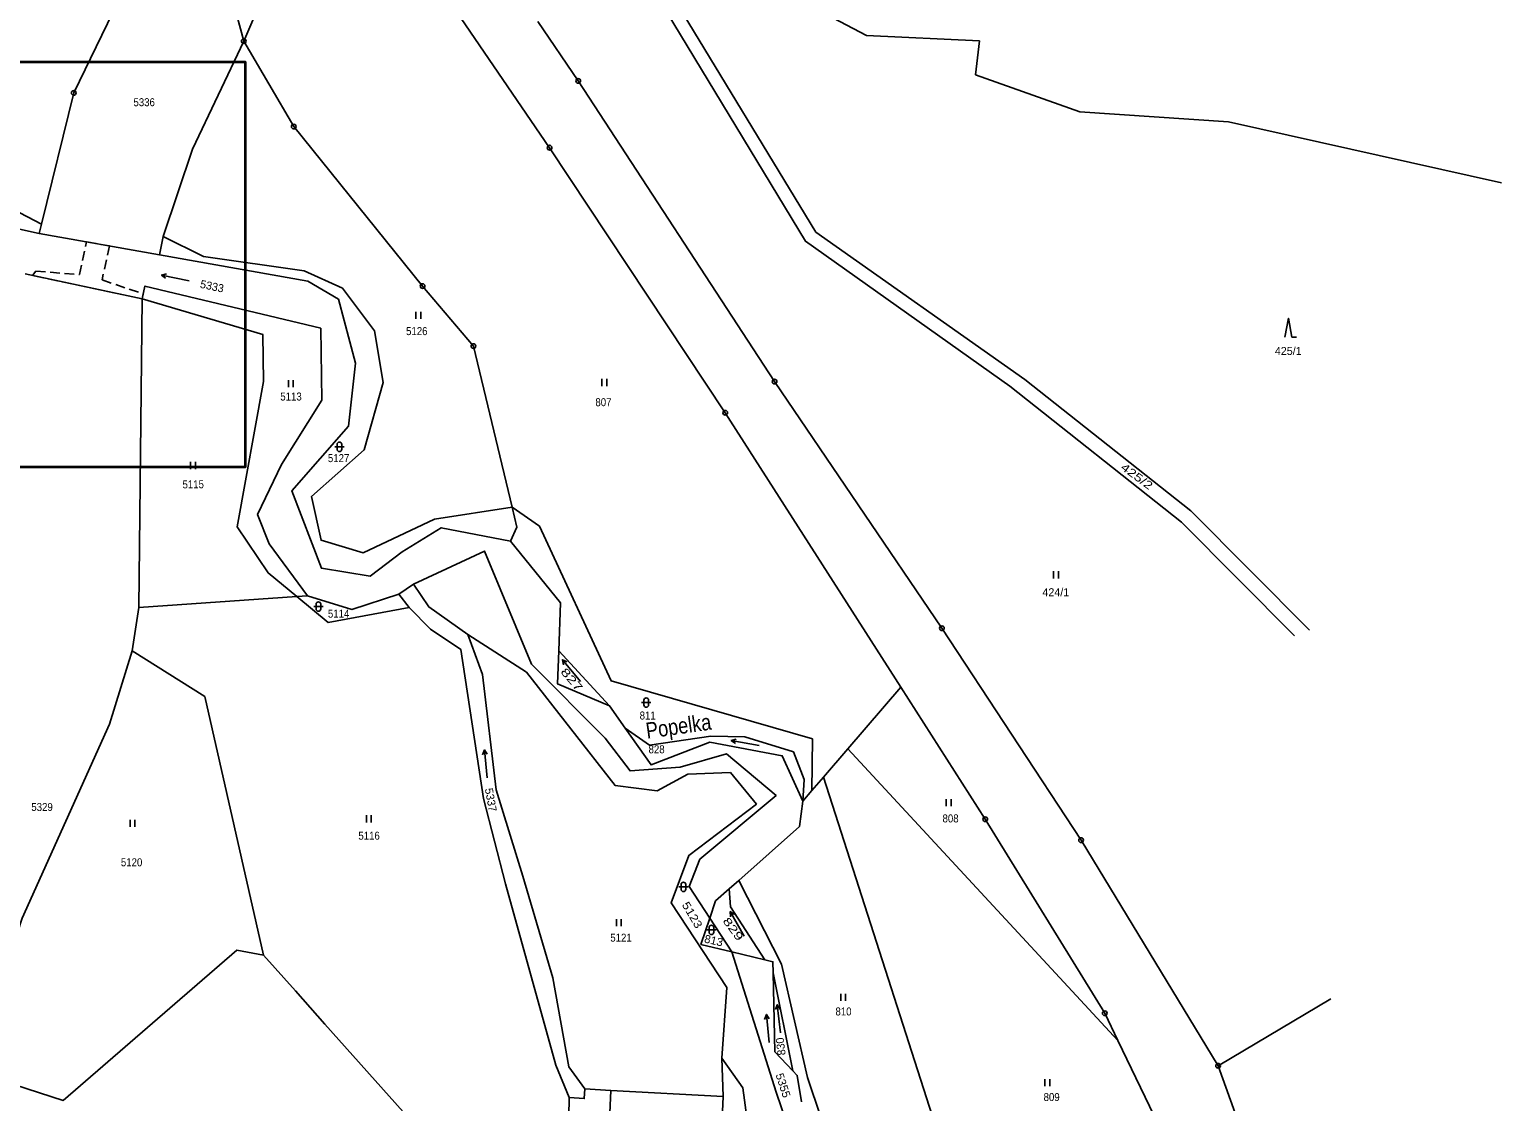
# Model space of a CAD drawing. Extents: x -665688 to -664583, y -1006118 to -1004927.
# Drawn here: x -664897.5 to -664584.8, y -1005404.2 to -1005176.4 of the extents above; entities that cross this region are included whole.
import ezdxf
from ezdxf.enums import TextEntityAlignment as Align

# ---------------------------------------------------------------- set-up
doc = ezdxf.new("R2010")
doc.units = 0
doc.header["$LTSCALE"] = 0.68
doc.linetypes.add('MEDIUM_DASHED', pattern=[4.5, 3, -1.5])
for name, color, linetype, lineweight in [('1', 7, 'Continuous', 25), ('13', 7, 'Continuous', 25), ('24', 7, 'Continuous', 25), ('25', 7, 'Continuous', 25), ('27', 7, 'MEDIUM_DASHED', 25), ('55', 7, 'Continuous', 35)]:
    doc.layers.add(name, color=color, linetype=linetype, lineweight=lineweight)
doc.layers.add('15', color=7, linetype='Continuous')
doc.layers.add('18', color=7, linetype='Continuous')

msp = doc.modelspace()

# ---------------------------------------------------------------- linework, layer by layer
at = {"layer": '1'}
for p, q in [((-664851.93, -1005178.83), (-664836.36, -1005142.64)), ((-664746.72, -1005163.4), (-664719.7, -1005177.66)), ((-664762.2, -1005167.13), (-664730.44, -1005219.44)), ((-664719.7, -1005177.66), (-664695.7, -1005178.77)), ((-664695.7, -1005178.77), (-664696.56, -1005186.03)), ((-664642.85, -1005196.03), (-664584.83, -1005208.98)), ((-664894.9, -1005217.74), (-664895.39, -1005219.73)), ((-664869.85, -1005224.23), (-664895.39, -1005219.73)), ((-664730.44, -1005219.44), (-664686.09, -1005250.74)), ((-664815.88, -1005294.24), (-664819.04, -1005296.36)), ((-664838.44, -1005296.74), (-664840.64, -1005296.9)), ((-664819.04, -1005296.36), (-664816.8, -1005299.23)), ((-664774.3, -1005320.07), (-664785.06, -1005308.45)), ((-664712.42, -1005316.13), (-664723.68, -1005329.24)), ((-664712.42, -1005316.13), (-664694.47, -1005344.21)), ((-664723.68, -1005329.24), (-664666.29, -1005391.23)), ((-664728.86, -1005335.28), (-664731.31, -1005338.13)), ((-664669.09, -1005385.43), (-664694.47, -1005344.21)), ((-664674.11, -1005348.65), (-664645.03, -1005396.59)), ((-664752.97, -1005365.23), (-664748.29, -1005372.39)), ((-664735.31, -1005397.69), (-664739.51, -1005376.86)), ((-664669.09, -1005385.43), (-664666.29, -1005391.23)), ((-664621.12, -1005382.39), (-664645.03, -1005396.59)), ((-664666.29, -1005391.23), (-664645.34, -1005434.72)), ((-664645.03, -1005396.59), (-664637.3, -1005417.95))]:
    msp.add_line(p, q, dxfattribs=at)
for points in [[(-664895.39, -1005219.73), (-664908.63, -1005216.84), (-664915.67, -1005184.63), (-664927.97, -1005174.84), (-664931.29, -1005161.96), (-664923.13, -1005157.75), (-664909.4, -1005145.58), (-664903.94, -1005133.92), (-664903.15, -1005127.85), (-664912.19, -1005084.06), (-664891.68, -1005067.49), (-664871.95, -1005045.77), (-664858.98, -1005033.99), (-664851.57, -1005033.48)], [(-664894.9, -1005217.74), (-664907.14, -1005211.36), (-664904.2, -1005191.46), (-664923.77, -1005167.11), (-664902.42, -1005142.29), (-664899.45, -1005128.56), (-664907.27, -1005091.69), (-664905.43, -1005083.63), (-664892.51, -1005077.23), (-664870.34, -1005046.85), (-664858.99, -1005037.17), (-664850.64, -1005036.62)], [(-664786.99, -1005201.49), (-664820.71, -1005152.05), (-664821.82, -1005136.31)], [(-664861.71, -1005142.6), (-664872.63, -1005157.96), (-664888.06, -1005189.84), (-664894.9, -1005217.74)], [(-664628.82, -1005305.2), (-664652.8, -1005281.09), (-664689.29, -1005252.19), (-664732.62, -1005221.37), (-664763.66, -1005170.15), (-664809.24, -1005142.21)], [(-664789.5, -1005174.71), (-664780.9, -1005187.31), (-664739.22, -1005251.21), (-664703.67, -1005303.61), (-664674.11, -1005348.65)], [(-664869.03, -1005220.36), (-664862.83, -1005201.79), (-664851.93, -1005178.83)], [(-664696.56, -1005186.03), (-664674.4, -1005193.9), (-664642.85, -1005196.03)], [(-664786.99, -1005201.49), (-664749.69, -1005257.83), (-664712.42, -1005316.13)], [(-664795.31, -1005285.13), (-664810.01, -1005282.26), (-664818.31, -1005287.39), (-664825.12, -1005292.52), (-664835.46, -1005290.86), (-664841.73, -1005274.39), (-664829.67, -1005260.64), (-664828.21, -1005247.31), (-664831.83, -1005233.69), (-664838.37, -1005229.89), (-664869.85, -1005224.23), (-664869.03, -1005220.36)], [(-664869.03, -1005220.36), (-664860.47, -1005224.62), (-664839.09, -1005227.67), (-664830.98, -1005231.36), (-664824.16, -1005240.41), (-664822.32, -1005251.37), (-664826.34, -1005265.68), (-664837.54, -1005275.62), (-664835.51, -1005284.9), (-664826.58, -1005287.6), (-664811.45, -1005280.42), (-664794.96, -1005277.9)], [(-664898.36, -1005228.3), (-664873.52, -1005233.6), (-664874.22, -1005299.23)], [(-664838.44, -1005296.74), (-664846.52, -1005285.68), (-664849, -1005279.46), (-664843.95, -1005268.82), (-664835.37, -1005255.16), (-664835.59, -1005239.86), (-664872.94, -1005230.92), (-664873.52, -1005233.6)], [(-664840.64, -1005296.9), (-664846.76, -1005291.86), (-664853.34, -1005282.04), (-664847.77, -1005251.19), (-664847.92, -1005241.18), (-664873.52, -1005233.6)], [(-664686.09, -1005250.74), (-664650.85, -1005278.69), (-664625.64, -1005304.01)], [(-664794.96, -1005277.9), (-664789.11, -1005281.94), (-664773.95, -1005314.78), (-664731.18, -1005327.12), (-664731.31, -1005338.13), (-664733.25, -1005340.39)], [(-664815.88, -1005294.24), (-664800.81, -1005287.23), (-664790.83, -1005311.28), (-664775.22, -1005326.97), (-664769.91, -1005333.94), (-664759.27, -1005333.13), (-664749.4, -1005330.3), (-664738.9, -1005339.16), (-664755.06, -1005352.72), (-664757.37, -1005358.5), (-664752.97, -1005365.23)], [(-664804.34, -1005304.93), (-664812.66, -1005299.08), (-664815.88, -1005294.24)], [(-664875.64, -1005308.45), (-664874.22, -1005299.23), (-664840.64, -1005296.9)], [(-664840.64, -1005296.9), (-664833.99, -1005302.38), (-664816.8, -1005299.23)], [(-664819.04, -1005296.36), (-664828.98, -1005299.6), (-664838.44, -1005296.74)], [(-664816.8, -1005299.23), (-664812.3, -1005303.8), (-664805.87, -1005308.13), (-664801, -1005339.77), (-664796.34, -1005357.91), (-664785.7, -1005396.43), (-664782.81, -1005403.35)], [(-664750.42, -1005394.97), (-664749.38, -1005379.95), (-664761.15, -1005361.98), (-664757.43, -1005351.9), (-664743.09, -1005340.97), (-664748.6, -1005334.26), (-664757.62, -1005334.64), (-664764.12, -1005338.16), (-664773.09, -1005337.03), (-664791.93, -1005312.96), (-664804.34, -1005304.93)], [(-664779.5, -1005401.51), (-664782.89, -1005396.83), (-664786.34, -1005377.93), (-664792.69, -1005356.27), (-664798.34, -1005337.92), (-664801.27, -1005313.46), (-664804.34, -1005304.93)], [(-664911.11, -1005397.23), (-664908.16, -1005391.22), (-664903.76, -1005379.6), (-664898.99, -1005365.23), (-664880.44, -1005324.02), (-664875.64, -1005308.45)], [(-664875.64, -1005308.45), (-664860.2, -1005318.12), (-664847.73, -1005373.11)], [(-664733.25, -1005340.39), (-664732.92, -1005335.73), (-664735.2, -1005329.88), (-664745.53, -1005326.71), (-664752.77, -1005326.57), (-664765.81, -1005328.48), (-664770.92, -1005324.88)], [(-664699.45, -1005426.75), (-664728.86, -1005335.28), (-664723.68, -1005329.24)], [(-664746.83, -1005357.2), (-664737.74, -1005375.01), (-664732.19, -1005399.11), (-664729.38, -1005407.54), (-664719.28, -1005418.59), (-664699.45, -1005426.75)], [(-664741.29, -1005374.08), (-664748.55, -1005362.82), (-664748.83, -1005358.98)], [(-664847.73, -1005373.11), (-664853.38, -1005372.05), (-664890.31, -1005403.96), (-664911.11, -1005397.23)], [(-664748.29, -1005372.39), (-664738.86, -1005402.17), (-664734.19, -1005415.94), (-664744.63, -1005411.3)], [(-664812.89, -1005451.45), (-664811.38, -1005448.39), (-664809.91, -1005445.4), (-664807.84, -1005439.72), (-664801.49, -1005424.98), (-664834.73, -1005387.75), (-664840.95, -1005380.66), (-664847.73, -1005373.11)], [(-664750.42, -1005394.97), (-664750.16, -1005403.15), (-664774.02, -1005401.84), (-664779.5, -1005401.51)], [(-664744.63, -1005411.3), (-664745.94, -1005401.29), (-664750.42, -1005394.97)], [(-664774.02, -1005401.84), (-664774.38, -1005411.4), (-664782.97, -1005411.32), (-664782.81, -1005403.35)], [(-664782.81, -1005403.35), (-664779.62, -1005403.56), (-664779.5, -1005401.51)], [(-664750.04, -1005419.42), (-664749.75, -1005412.62), (-664750.53, -1005412.59), (-664750.16, -1005403.15)]]:
    msp.add_lwpolyline(points, dxfattribs=at)
at = {"layer": '13'}
for p, q in [((-664851.93, -1005178.83), (-664861.71, -1005142.6)), ((-664794.96, -1005277.9), (-664803.18, -1005243.67))]:
    msp.add_line(p, q, dxfattribs=at)
for points in [[(-664803.18, -1005243.67), (-664813.96, -1005230.9), (-664841.32, -1005197.02), (-664851.93, -1005178.83)], [(-664794.96, -1005277.9), (-664793.94, -1005282.14), (-664795.31, -1005285.13)], [(-664785.06, -1005308.45), (-664784.7, -1005298.23), (-664795.31, -1005285.13)], [(-664774.3, -1005320.07), (-664785.3, -1005315.45), (-664785.06, -1005308.45)], [(-664733.25, -1005340.39), (-664737.57, -1005330.7), (-664752.93, -1005327.83), (-664765.45, -1005332.65), (-664770.92, -1005324.88), (-664774.3, -1005320.07)], [(-664746.83, -1005357.2), (-664733.95, -1005345.75), (-664733.25, -1005340.39)], [(-664752.97, -1005365.23), (-664751.74, -1005361.56), (-664748.83, -1005358.98), (-664746.83, -1005357.2)], [(-664748.29, -1005372.39), (-664754.85, -1005370.8), (-664752.97, -1005365.23)], [(-664739.51, -1005376.86), (-664739.56, -1005374.5), (-664741.29, -1005374.08), (-664748.29, -1005372.39)], [(-664735.31, -1005397.69), (-664739.14, -1005393.64), (-664739.51, -1005376.86)], [(-664733.49, -1005404.29), (-664734.41, -1005398.64), (-664735.31, -1005397.69)]]:
    msp.add_lwpolyline(points, dxfattribs=at)
at = {"layer": '24'}
for centre, radius in [((-664851.93, -1005178.83), 0.5), ((-664851.93, -1005178.83), 0.032), ((-664780.9, -1005187.31), 0.5), ((-664780.9, -1005187.31), 0.032), ((-664888.06, -1005189.84), 0.5), ((-664888.06, -1005189.84), 0.032), ((-664841.32, -1005197.02), 0.5), ((-664841.32, -1005197.02), 0.032), ((-664786.99, -1005201.49), 0.5), ((-664786.99, -1005201.49), 0.032), ((-664813.96, -1005230.9), 0.5), ((-664813.96, -1005230.9), 0.032), ((-664803.18, -1005243.67), 0.5), ((-664803.18, -1005243.67), 0.032), ((-664739.22, -1005251.21), 0.5), ((-664739.22, -1005251.21), 0.032), ((-664749.69, -1005257.83), 0.5), ((-664749.69, -1005257.83), 0.032), ((-664703.67, -1005303.61), 0.5), ((-664703.67, -1005303.61), 0.032), ((-664694.47, -1005344.21), 0.5), ((-664694.47, -1005344.21), 0.032), ((-664674.11, -1005348.65), 0.5), ((-664674.11, -1005348.65), 0.032), ((-664669.09, -1005385.43), 0.5), ((-664669.09, -1005385.43), 0.032), ((-664645.03, -1005396.59), 0.5), ((-664645.03, -1005396.59), 0.032)]:
    msp.add_circle(centre, radius, dxfattribs=at)
at = {"layer": '25'}
for p, q in [((-664863.533, -1005229.768), (-664869.407, -1005228.552)), ((-664815.367, -1005237.885), (-664815.367, -1005236.385)), ((-664814.333, -1005237.885), (-664814.333, -1005236.385)), ((-664842.477, -1005252.375), (-664842.477, -1005250.875)), ((-664841.443, -1005252.375), (-664841.443, -1005250.875)), ((-664775.877, -1005252.145), (-664775.877, -1005250.645)), ((-664774.843, -1005252.145), (-664774.843, -1005250.645)), ((-664832.62, -1005265.06), (-664830.62, -1005265.06)), ((-664832.12, -1005265.56), (-664832.12, -1005264.56)), ((-664831.12, -1005264.56), (-664831.12, -1005265.56)), ((-664863.247, -1005269.785), (-664863.247, -1005268.285)), ((-664862.213, -1005269.785), (-664862.213, -1005268.285)), ((-664679.957, -1005293.015), (-664679.957, -1005291.515)), ((-664678.923, -1005293.015), (-664678.923, -1005291.515)), ((-664837.09, -1005299.01), (-664835.09, -1005299.01)), ((-664836.59, -1005299.51), (-664836.59, -1005298.51)), ((-664835.59, -1005298.51), (-664835.59, -1005299.51)), ((-664780.466, -1005314.958), (-664784.274, -1005310.322)), ((-664767.46, -1005319.4), (-664765.46, -1005319.4)), ((-664766.96, -1005319.9), (-664766.96, -1005318.9)), ((-664765.96, -1005318.9), (-664765.96, -1005319.9)), ((-664742.514, -1005328.5), (-664748.426, -1005327.48)), ((-664800.243, -1005335.426), (-664800.817, -1005329.454)), ((-664702.777, -1005341.435), (-664702.777, -1005339.935)), ((-664701.743, -1005341.435), (-664701.743, -1005339.935)), ((-664876.087, -1005345.795), (-664876.087, -1005344.295)), ((-664875.053, -1005345.795), (-664875.053, -1005344.295)), ((-664825.897, -1005344.865), (-664825.897, -1005343.365)), ((-664824.863, -1005344.865), (-664824.863, -1005343.365)), ((-664759.58, -1005358.58), (-664757.58, -1005358.58)), ((-664759.08, -1005359.08), (-664759.08, -1005358.08)), ((-664758.08, -1005358.08), (-664758.08, -1005359.08)), ((-664772.817, -1005366.945), (-664772.817, -1005365.445)), ((-664771.783, -1005366.945), (-664771.783, -1005365.445)), ((-664745.66, -1005369.033), (-664748.64, -1005363.827)), ((-664753.64, -1005367.72), (-664751.64, -1005367.72)), ((-664753.14, -1005368.22), (-664753.14, -1005367.22)), ((-664752.14, -1005367.22), (-664752.14, -1005368.22)), ((-664725.177, -1005382.775), (-664725.177, -1005381.275)), ((-664724.143, -1005382.775), (-664724.143, -1005381.275)), ((-664737.971, -1005389.57), (-664738.649, -1005383.61)), ((-664740.342, -1005391.654), (-664740.958, -1005385.686)), ((-664681.827, -1005400.955), (-664681.827, -1005399.455)), ((-664680.793, -1005400.955), (-664680.793, -1005399.455))]:
    msp.add_line(p, q, dxfattribs=at)
for points in [[(-664868.529, -1005229.244), (-664869.407, -1005228.552), (-664868.327, -1005228.265)], [(-664630.85, -1005241.73), (-664630.1, -1005237.73), (-664629.35, -1005241.73), (-664628.35, -1005241.73)], [(-664784.025, -1005311.412), (-664784.274, -1005310.322), (-664783.253, -1005310.778)], [(-664747.525, -1005328.142), (-664748.426, -1005327.48), (-664747.355, -1005327.157)], [(-664801.219, -1005330.498), (-664800.817, -1005329.454), (-664800.224, -1005330.402)], [(-664748.577, -1005364.943), (-664748.64, -1005363.827), (-664747.71, -1005364.446)], [(-664739.033, -1005384.66), (-664738.649, -1005383.61), (-664738.04, -1005384.547)], [(-664741.352, -1005386.732), (-664740.958, -1005385.686), (-664740.359, -1005386.63)]]:
    msp.add_lwpolyline(points, dxfattribs=at)
for centre, start, end in [((-664831.62, -1005264.56), 0.101, 180.00143), ((-664831.62, -1005265.56), 180.10243, 0.00286), ((-664836.09, -1005298.51), 0.101, 180.00143), ((-664836.09, -1005299.51), 180.10243, 0.00286), ((-664766.46, -1005318.9), 0.101, 180.00143), ((-664766.46, -1005319.9), 180.10243, 0.00286), ((-664758.58, -1005358.08), 0.101, 180.00143), ((-664758.58, -1005359.08), 180.10243, 0.00286), ((-664752.64, -1005367.22), 0.101, 180.00143), ((-664752.64, -1005368.22), 180.10243, 0.00286)]:
    msp.add_arc(centre, 0.5, start, end, dxfattribs=at)
at = {"layer": '27'}
msp.add_lwpolyline([(-664896.8, -1005228.63), (-664896.11, -1005227.75), (-664886.82, -1005228.44), (-664885.33, -1005221.5), (-664880.46, -1005222.36), (-664882.04, -1005229.6), (-664873.3, -1005232.57), (-664873.52, -1005233.6)], close=True, dxfattribs=at)
at = {"layer": '55'}
msp.add_lwpolyline([(-664910.13, -1005269.36), (-664910.13, -1005183.26), (-664851.63, -1005183.26), (-664851.63, -1005269.36)], close=True, dxfattribs=at)

# ---------------------------------------------------------------- texts
at = {"layer": '15', "width": 0.85}
msp.add_text('Popelka', height=3.4, rotation=8.1, dxfattribs=at).set_placement((-664759.3795, -1005326.1162), align=Align.CENTER)
at = {"layer": '18', "width": 0.9}
for s, p in [('5336', (-664873.0895, -1005192.68)), ('5126', (-664815.1995, -1005241.32)), ('5113', (-664841.9095, -1005255.22)), ('807', (-664775.5595, -1005256.43)), ('5127', (-664831.7995, -1005268.31)), ('5114', (-664831.7995, -1005301.37)), ('811', (-664766.1595, -1005323.01)), ('5329', (-664894.7795, -1005342.45)), ('808', (-664701.8395, -1005344.88)), ('5116', (-664825.3295, -1005348.55)), ('5120', (-664875.7595, -1005354.2)), ('5121', (-664771.8295, -1005370.22)), ('810', (-664724.5795, -1005385.9)), ('809', (-664680.3795, -1005404.09))]:
    msp.add_text(s, height=1.7, dxfattribs=at).set_placement(p, align=Align.CENTER)
at = {"layer": '18'}
for s, rotation, p in [('5333', 348.003, (-664858.8552, -1005231.7656)), ('5337', 280.202, (-664800.3055, -1005340.2399))]:
    msp.add_text(s, height=1.7, rotation=rotation, dxfattribs=at).set_placement(p, align=Align.CENTER)
for s, p in [('425/1', (-664630.13, -1005245.54)), ('424/1', (-664679.49, -1005296.81))]:
    msp.add_text(s, height=1.7, dxfattribs=at).set_placement(p, align=Align.CENTER)
for s, rotation, width, p in [('425/2', 323.503, 1.35, (-664662.7766, -1005272.012)), ('5115', 0.5, 0.9, (-664862.6699, -1005273.8771)), ('5123', 300.402, 1.2, (-664757.4309, -1005364.9798)), ('5355', 288.002, 1.05, (-664738.2034, -1005401.0218))]:
    msp.add_text(s, height=1.7, rotation=rotation, dxfattribs=dict(at, width=width)).set_placement(p, align=Align.CENTER)
for s, rotation, width, p in [('827', 310.702, 1.5, (-664784.788, -1005312.931)), ('829', 306.802, 1.45, (-664750.341, -1005365.84)), ('813', 347.203, 1.05, (-664754.271, -1005370.37))]:
    msp.add_text(s, height=1.7, rotation=rotation, dxfattribs=dict(at, width=width)).set_placement(p)
at = {"layer": '18', "width": 0.9}
msp.add_text('828', height=1.7, dxfattribs=at).set_placement((-664765.98, -1005330.19))
at = {"layer": '18'}
msp.add_text('830', height=1.7, rotation=96.701, dxfattribs=at).set_placement((-664736.861, -1005394.285))

doc.saveas('drawing.dxf')
